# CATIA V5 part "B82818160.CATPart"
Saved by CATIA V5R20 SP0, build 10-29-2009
Part number: B82818160
Revision: 3
Definition: design
Nomenclature: B82818160
Source: made
Description: NOT SPECIFIED
Bounding box of the stored display mesh (mm): x -10.833 to 10.833, y -11 to 11, z 0 to 160
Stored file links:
  C:\Users\Raffaele\Desktop\3D X SITO CF\BOLEX\7-PILLAR REF 828\B82818160.CATPart
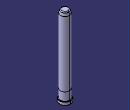
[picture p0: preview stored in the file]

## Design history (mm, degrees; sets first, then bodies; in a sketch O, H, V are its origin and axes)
Body1 "MANIFOLD_SOLID_BREP #450" (main body)
  Solid1: solid without history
